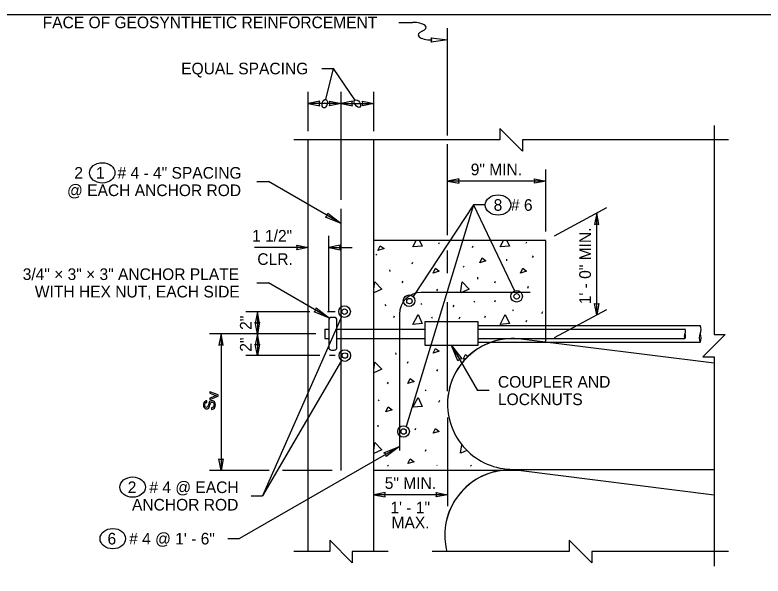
# Model space of a CAD drawing. Extents: x 99862 to 104211, y 98939 to 105076.
# Drawn here: x 100393 to 101422, y 104304 to 105076 of the extents above; entities that cross this region are included whole.
import ezdxf

# ---------------------------------------------------------------- set-up
doc = ezdxf.new("R2010")
doc.units = 0
for name, color, linetype in [('Level 1', 7, 'Continuous'), ('Level 10', 7, 'Continuous'), ('Level 15', 7, 'Continuous'), ('Level 16', 7, 'Continuous'), ('Level 19', 7, 'Continuous'), ('Level 20', 7, 'Continuous'), ('Level 24', 7, 'Continuous'), ('Level 3', 7, 'Continuous'), ('Level 6', 7, 'Continuous'), ('Level 8', 7, 'Continuous')]:
    doc.layers.add(name, color=color, linetype=linetype)

msp = doc.modelspace()

# ---------------------------------------------------------------- linework, layer by layer
at = {"layer": 'Level 1'}
msp.add_lwpolyline([(99862, 102999.5), (103151, 102999.5), (103151, 105075.5), (99862, 105075.5)], close=True, dxfattribs=at)
at = {"layer": 'Level 10'}
msp.add_line((100841.7, 104449), (100841.7, 104809), dxfattribs=at)
for points in [[(101101.9, 104693.9), (100951.9, 104693.9)], [(100921.9, 104663.9), (100921.9, 104476.4)]]:
    msp.add_lwpolyline(points, dxfattribs=at)
for centre in [(101083.1, 104688.5), (100935.7, 104681.9), (100846.5, 104667.4), (100846.9, 104607), (100927.6, 104502.5)]:
    msp.add_circle(centre, 3.75, dxfattribs=at)
msp.add_arc((100951.9, 104663.9), 30, 90, 180, dxfattribs=at)
at = {"layer": 'Level 15'}
for p, q in [((100921.2, 105065.2), (100939.8, 105065.2)), ((100988.2, 104909.6), (100988.2, 105057.2)), ((100815.1, 105001.8), (100831.1, 105001.8)), ((100820.6, 104959.4), (100831.1, 105001.8)), ((100860.8, 104958.6), (100831.1, 105001.8)), ((100796.7, 104915.6), (100796.7, 104969.6)), ((100841.7, 104821), (100841.7, 104969.6)), ((100886.7, 104915.6), (100886.7, 104969.6)), ((100841.7, 104953.6), (100886.7, 104953.6)), ((100988.2, 104772.6), (100988.2, 104897.6)), ((101123.2, 104777.4), (101123.2, 104863)), ((100725.9, 104846.3), (100741.9, 104846.3)), ((100841.7, 104788.7), (100741.9, 104846.3)), ((101123.2, 104847), (100988.2, 104847)), ((101024, 104814.1), (100931, 104509.6)), ((101024, 104814.1), (100940.9, 104688.1)), ((101040, 104814.1), (101024, 104814.1)), ((101024, 104814.1), (101080.3, 104696)), ((101135.2, 104771.8), (101207.3, 104810.5)), ((101193.2, 104663), (101193.2, 104802.9)), ((100824.8, 104667.7), (100824.8, 104771.7)), ((100796.7, 104755.7), (100722.8, 104755.7)), ((100824.8, 104755.7), (100856.8, 104755.7)), ((100988.2, 104720.5), (100988.2, 104751.5)), ((100725.9, 104706.9), (100741.9, 104706.9)), ((100825.9, 104658.4), (100741.9, 104706.9)), ((100988.2, 104557.8), (100988.2, 104680.6)), ((101135.2, 104631.9), (101207.3, 104670.5)), ((100799, 104667), (100710.7, 104667)), ((100726.7, 104667), (100726.7, 104637)), ((100842.5, 104660.3), (100733.9, 104413.8)), ((100833.4, 104667), (100823, 104667)), ((100807.2, 104637), (100660.7, 104637)), ((100676.7, 104637), (100676.7, 104449)), ((100726.7, 104637), (100726.7, 104607)), ((100993.6, 104620.7), (101029.4, 104558.8)), ((100812.4, 104607), (100710.7, 104607)), ((100833.4, 104607), (100825.6, 104607)), ((100842.5, 104600.2), (100733.9, 104413.8)), ((101045.4, 104558.8), (101029.4, 104558.8)), ((100988.2, 104521.8), (100988.2, 104399.6)), ((100921.9, 104482.1), (100702, 104355.1)), ((100742.9, 104449), (100660.7, 104449)), ((100829.7, 104449), (100761.2, 104449)), ((100717.9, 104413.8), (100733.9, 104413.8)), ((100988.2, 104415.6), (100886.7, 104415.6)), ((100686, 104355.1), (100702, 104355.1))]:
    msp.add_line(p, q, dxfattribs=at)
for points in [[(100988.2, 105041.2), (100965.4, 105038.2), (100966.4, 105041.2), (100965.4, 105044.2)], [(100796.7, 104953.6), (100812.4, 104950.5), (100811.7, 104953.6), (100812.4, 104956.7)], [(100841.7, 104953.6), (100826, 104950.5), (100826.7, 104953.6), (100826, 104956.7)], [(100841.7, 104953.6), (100857.4, 104950.5), (100856.7, 104953.6), (100857.4, 104956.7)], [(100886.7, 104953.6), (100871, 104950.5), (100871.7, 104953.6), (100871, 104956.7)], [(100988.2, 104847), (101003.9, 104843.9), (101003.2, 104847), (101003.9, 104850.1)], [(101123.2, 104847), (101107.5, 104843.9), (101108.2, 104847), (101107.5, 104850.1)], [(100841.7, 104788.7), (100820.4, 104797.5), (100822.8, 104799.6), (100823.4, 104802.7)], [(101193.2, 104802.9), (101190.1, 104787.2), (101193.2, 104788), (101196.3, 104787.2)], [(100796.7, 104755.7), (100781, 104752.6), (100781.7, 104755.7), (100781, 104758.8)], [(100824.8, 104755.7), (100840.5, 104752.6), (100839.8, 104755.7), (100840.5, 104758.8)], [(101193.2, 104663), (101190.1, 104678.7), (101193.2, 104678), (101196.3, 104678.7)], [(100825.9, 104658.4), (100804.6, 104667.2), (100807, 104669.3), (100807.6, 104672.4)], [(100726.7, 104667), (100723.6, 104651.2), (100726.7, 104652), (100729.8, 104651.2)], [(100726.7, 104637), (100723.6, 104652.7), (100726.7, 104652), (100729.8, 104652.7)], [(100676.7, 104637), (100673.6, 104621.2), (100676.7, 104622), (100679.8, 104621.2)], [(100726.7, 104637), (100723.6, 104621.2), (100726.7, 104622), (100729.8, 104621.2)], [(100726.7, 104607), (100723.6, 104622.7), (100726.7, 104622), (100729.8, 104622.7)], [(100993.6, 104620.7), (101007.6, 104602.5), (101004.5, 104601.9), (101002.4, 104599.5)], [(100921.9, 104482.1), (100903.6, 104468.1), (100903.1, 104471.2), (100900.7, 104473.3)], [(100676.7, 104449), (100673.6, 104464.7), (100676.7, 104464), (100679.8, 104464.7)], [(100886.7, 104415.6), (100902.4, 104412.5), (100901.7, 104415.6), (100902.4, 104418.6)], [(100988.2, 104415.6), (100972.5, 104412.5), (100973.2, 104415.6), (100972.5, 104418.6)]]:
    msp.add_lwpolyline(points, close=True, dxfattribs=at)
for points in [[(100841.7, 104953.6), (100796.7, 104953.6)], [(101374.5, 104903.6), (101091.1, 104903.6), (101091.1, 104888.1), (101060.1, 104919.1), (101060.1, 104903.6), (100776.7, 104903.6)], [(101354.5, 104923.6), (101354.5, 104636), (101370, 104636), (101339.1, 104605.1), (101354.5, 104605.1), (101354.5, 104317.5)], [(100906.7, 104337.5), (100857.2, 104337.5), (100857.2, 104322), (100826.2, 104353), (100826.2, 104337.5), (100776.7, 104337.5)], [(101374.5, 104337.5), (101186.3, 104337.5), (101186.3, 104322), (101155.3, 104353), (101155.3, 104337.5), (100967.1, 104337.5)]]:
    msp.add_lwpolyline(points, dxfattribs=at)
for centre in [(100935.3, 104682.4), (101083.1, 104688.5), (100846.5, 104667.4), (100846.9, 104607), (100927.6, 104502.5)]:
    msp.add_circle(centre, 8, dxfattribs=at)
for centre, start_param, end_param in [((100939.9, 105058.2), 5.497747, 7.861127), ((100966.4, 105048.2), 2.356226, 4.712389)]:
    msp.add_ellipse(centre, major_axis=(18.7, 0), ratio=0.375, start_param=start_param, end_param=end_param, dxfattribs=at)
for centre, major_axis in [((100819.2, 104953.6), (1.44, 5.82)), ((100864.2, 104953.6), (-3.4, 4.95))]:
    msp.add_ellipse(centre, major_axis=major_axis, ratio=0.57735, dxfattribs=at)
at = {"layer": 'Level 16'}
for p, q in [((100976.3, 104760.7), (100977.1, 104762.6)), ((101096.3, 104761.5), (101097.1, 104763.4)), ((101022.2, 104755.4), (101023.2, 104757.8)), ((100889.6, 104746.5), (100890.6, 104744.9)), ((101105.1, 104741.9), (101106.2, 104744.3)), ((100939.5, 104733.2), (100940.6, 104735.6)), ((101069, 104739.5), (101069.3, 104737.1)), ((100908.5, 104725.1), (100908.8, 104722.7)), ((101009.6, 104730), (101010.6, 104728.4)), ((101029.1, 104714.6), (101029.4, 104712.2)), ((100925.9, 104706.8), (100927, 104709.2)), ((101053.1, 104706.8), (101054.2, 104709.2)), ((101098.5, 104699.8), (101099.5, 104702.2)), ((100973.6, 104695.9), (100974.7, 104698.3)), ((100951.4, 104678.8), (100952.5, 104677.2)), ((101024.1, 104682.2), (101025.2, 104680.6)), ((101053.1, 104680.7), (101054.2, 104683.1)), ((100902.1, 104677), (100903.1, 104675.4)), ((100996, 104673.9), (100997, 104676.3)), ((101077.3, 104670.2), (101078.4, 104668.6)), ((100914.3, 104659.4), (100915.4, 104661.8)), ((100966, 104660.1), (100967.1, 104658.5)), ((101004.3, 104657.7), (101005.4, 104660.1)), ((101039.4, 104659.4), (101040.5, 104661.8)), ((101117.8, 104665), (101118.9, 104667.4)), ((101096.3, 104653.3), (101097.3, 104655.7)), ((100916.5, 104610.7), (100916.8, 104608.3)), ((100933.1, 104596.5), (100934.2, 104598.9)), ((100973.6, 104585.6), (100974.7, 104588)), ((100905.7, 104568.1), (100906.8, 104570.5)), ((100957.3, 104559.9), (100958.4, 104558.3)), ((100892.8, 104546.3), (100893.9, 104544.7)), ((100976.3, 104543), (100977.3, 104545.4)), ((100892.1, 104511.4), (100892.4, 104509)), ((100943.4, 104504.9), (100944.4, 104507.3)), ((100957.6, 104475.4), (100958.7, 104477.8)), ((100905.4, 104456.4), (100906.5, 104454.9)), ((100973.3, 104456.4), (100973.7, 104455.8)), ((101019.5, 104456.4), (101020.6, 104454.9))]:
    msp.add_line(p, q, dxfattribs=at)
for points in [[(100940.3, 104756.4), (100945.1, 104765.4)], [(100949.5, 104765.4), (100953.1, 104757.4), (100940.6, 104756.4)], [(101060.3, 104756.4), (101065.1, 104765.4)], [(101069.5, 104765.4), (101073.1, 104757.4), (101060.6, 104756.4)], [(100892.5, 104751.4), (100895.7, 104758.1), (100901.1, 104754.1), (100892.5, 104751.4)], [(101032.4, 104734.6), (101035.6, 104741.3), (101040.9, 104737.3), (101032.4, 104734.6)], [(100968.3, 104720.5), (100971.5, 104727.2), (100976.8, 104723.2), (100968.3, 104720.5)], [(101088.3, 104720.5), (101091.5, 104727.2), (101096.8, 104723.2), (101088.3, 104720.5)], [(100886.7, 104698.1), (100888.1, 104708.3), (100897.7, 104698.5), (100886.7, 104693.4)], [(101006, 104693.1), (101008.1, 104708.3), (101017.7, 104698.5), (101006.2, 104693.2)], [(100940.3, 104649.8), (100947.5, 104663.4), (100953.1, 104650.9), (100940.6, 104649.8)], [(101060.3, 104649.8), (101067.5, 104663.4), (101073.1, 104650.9), (101060.6, 104649.8)], [(100968.3, 104610.3), (100971.5, 104616.9), (100976.8, 104612.9), (100968.3, 104610.3)], [(101009.6, 104601.9), (101012.8, 104608.5), (101016.3, 104605.9)], [(100886.7, 104587.8), (100888.1, 104598.1), (100897.7, 104588.2), (100886.7, 104583.2)], [(101013.5, 104603.1), (101009.6, 104601.9)], [(100933.6, 104568.6), (100936.8, 104575.2), (100942.2, 104571.2), (100933.6, 104568.6)], [(100940.3, 104535.8), (100947.5, 104549.4), (100953.1, 104536.9), (100940.6, 104535.8)], [(100903.3, 104529.7), (100906.5, 104536.4), (100911.8, 104532.4), (100903.3, 104529.7)], [(100968.3, 104500), (100971.5, 104506.7), (100976.8, 104502.7), (100968.3, 104500)], [(100886.7, 104477), (100888.1, 104487.2), (100897.7, 104477.4), (100886.7, 104472.3)], [(101006, 104472.6), (101007.6, 104484.3)], [(101014.6, 104476.6), (101006.2, 104472.7)], [(100933.6, 104458.3), (100936.8, 104465), (100942.2, 104461), (100933.6, 104458.3)]]:
    msp.add_lwpolyline(points, dxfattribs=at)
at = {"layer": 'Level 19'}
msp.add_lwpolyline([(101078.4, 104449.6), (101078.4, 104450.4)], dxfattribs=at)
for centre, start, end in [((101078.1, 104540.4), 90.0973, 176.5425), ((101078.1, 104540.4), 176.5425, 270.21), ((101074.3, 104359.7), 87.4147, 176.5425), ((101074.3, 104359.7), 176.5425, 194.2759)]:
    msp.add_arc(centre, 90, start, end, dxfattribs=at)
at = {"layer": 'Level 20'}
for centre in [(100513.4, 104858.3), (101057.5, 104814.1), (100555.2, 104426), (100527.9, 104355.1)]:
    msp.add_ellipse(centre, major_axis=(-17.5, 0), ratio=0.8, dxfattribs=at)
at = {"layer": 'Level 24'}
msp.add_line((101078.4, 104450.4), (101354.5, 104450.4), dxfattribs=at)
for points in [[(101354.5, 104596.3), (101089.2, 104629.7)], [(101354.5, 104415.1), (101085.5, 104449)]]:
    msp.add_lwpolyline(points, dxfattribs=at)
for centre, start, end in [((101078.1, 104540.4), 82.875, 176.5425), ((101078.1, 104540.4), 176.5425, 270.21), ((101074.3, 104359.7), 82.875, 176.5425), ((101074.3, 104359.7), 176.5425, 194.276)]:
    msp.add_arc(centre, 90, start, end, dxfattribs=at)
at = {"layer": 'Level 3'}
for p, q in [((100796.7, 104337.5), (100796.7, 104903.6)), ((100886.7, 104337.5), (100886.7, 104903.6))]:
    msp.add_line(p, q, dxfattribs=at)
for points in [[(100672.6, 104550.9), (100672.6, 104552.8), (100661.1, 104557.1), (100661.1, 104555.2), (100668.1, 104552.5), (100670.3, 104551.8), (100668, 104551.1), (100661.1, 104548.4), (100661.1, 104546.5)], [(100663.5, 104532.9), (100665, 104533.2), (100666.3, 104533.8), (100667.5, 104534.7), (100668.3, 104535.9), (100668.7, 104537.5), (100668.9, 104539.4), (100668.7, 104540.9), (100668.3, 104542.3), (100667.5, 104543.5), (100666.5, 104544.3), (100665.4, 104544.8), (100664.2, 104545), (100663, 104544.8), (100661.9, 104544.4), (100661, 104543.6), (100660.3, 104542.4), (100659.3, 104539.1), (100658.7, 104537.2), (100658.2, 104536.2), (100657.6, 104535.8), (100656.8, 104535.6), (100655.9, 104535.8), (100655.1, 104536.5), (100654.6, 104537.5), (100654.4, 104539), (100654.6, 104540.5), (100655.1, 104541.6), (100655.9, 104542.3), (100657.1, 104542.6), (100657.1, 104544.7), (100655.9, 104544.5), (100654.7, 104544), (100653.8, 104543.1), (100653.1, 104541.9), (100652.7, 104540.5), (100652.6, 104538.9), (100652.7, 104537.5), (100653.1, 104536.1), (100653.8, 104535), (100654.7, 104534.2), (100655.8, 104533.7), (100656.9, 104533.5), (100658, 104533.7), (100658.9, 104534.1), (100659.7, 104534.8), (100660.4, 104535.8), (100660.9, 104537), (100661.4, 104538.7), (100662.1, 104541.3), (100662.6, 104542.1), (100663.1, 104542.6), (100663.7, 104542.8), (100664.4, 104542.9), (100665.1, 104542.8), (100665.8, 104542.5), (100666.3, 104542), (100666.7, 104541.2), (100667, 104540.3), (100667.1, 104539.3), (100667, 104538.1), (100666.6, 104537.1), (100666.1, 104536.2), (100665.4, 104535.6), (100664.5, 104535.3), (100663.5, 104535)]]:
    msp.add_lwpolyline(points, close=True, dxfattribs=at)
at = {"layer": 'Level 6'}
for p, q in [((101123.2, 104765.4), (100886.7, 104765.4)), ((101123.2, 104625.4), (101123.2, 104765.4)), ((101085.5, 104449), (100886.7, 104449))]:
    msp.add_line(p, q, dxfattribs=at)
at = {"layer": 'Level 8'}
for p, q in [((100832.3, 104659.5), (100828.5, 104659.5)), ((100824.8, 104655.7), (100824.8, 104618.2)), ((100836, 104618.2), (100836, 104655.7)), ((101029.9, 104648.5), (101335.4, 104648.5)), ((100819.2, 104643.5), (100819.2, 104630.4)), ((100819.2, 104643.5), (100824.8, 104643.5)), ((100836, 104643.5), (100957.3, 104643.5)), ((101029.9, 104643.5), (101314.4, 104643.5)), ((100819.2, 104630.4), (100824.8, 104630.4)), ((100836, 104630.4), (100957.3, 104630.4)), ((101029.9, 104630.4), (101314.4, 104630.4)), ((101029.9, 104625.4), (101335.4, 104625.4)), ((100828.5, 104614.5), (100832.3, 104614.5))]:
    msp.add_line(p, q, dxfattribs=at)
msp.add_lwpolyline([(100957.3, 104653.7), (101029.9, 104653.7), (101029.9, 104620.7), (100957.3, 104620.7)], close=True, dxfattribs=at)
for centre, radius, start, end in [((100828.5, 104655.7), 3.75, 90, 180), ((100832.3, 104655.7), 3.75, 0, 90), ((101325.4, 104642.7), 11.5, 330, 30), ((101308.7, 104640.3), 6.56, 330, 30), ((101320.1, 104633.7), 6.56, 150, 210), ((101308.7, 104633.7), 6.56, 330, 30), ((101345.4, 104631.2), 11.5, 150, 210), ((101325.4, 104631.2), 11.5, 330, 30), ((100828.5, 104618.2), 3.75, 180, 270), ((100832.3, 104618.2), 3.75, 270, 0)]:
    msp.add_arc(centre, radius, start, end, dxfattribs=at)

# ---------------------------------------------------------------- texts
at = {"layer": 'Level 20'}
for s, p in [('FACE OF GEOSYNTHETIC REINFORCEMENT', (100431.5, 105057.2)), ('EQUAL SPACING', (100621.9, 104993.8)), ('2   1   # 4 - 4" SPACING', (100475, 104850.3)), ('9" MIN.', (101020, 104855)), ('@ EACH ANCHOR ROD', (100465, 104826.3)), ('1 1/2"', (100719.3, 104763.7)), ('CLR.', (100726.6, 104731.7)), (' 3/4" × 3" × 3" ANCHOR PLATE ', (100398.1, 104710.9)), ('WITH HEX NUT, EACH SIDE', (100420.7, 104686.9)), ('2   # 4 @ EACH', (100548.4, 104417.8)), ('5" MIN.', (100901.8, 104423.6)), ('ANCHOR ROD', (100554.3, 104393.8)), ('1\' - 1"', (100909.5, 104389.9)), ('MAX.', (100911.1, 104369.2)), (' 6   # 4 @ 1\' - 6"', (100514.7, 104347.1))]:
    msp.add_text(s, height=16, dxfattribs=at).set_placement(p)
for s, rotation, p in [('8  # 6', 360, (101051.5, 104806.1)), ('1\' - 0" MIN.', 90, (101185.2, 104677.5)), ('2"', 90, (100718.7, 104642.3)), ('2"', 90, (100718.7, 104612.3)), ('COUPLER AND', 360, (101057.4, 104562.8)), ('LOCKNUTS', 360, (101057.4, 104538.8))]:
    msp.add_text(s, height=16, rotation=rotation, dxfattribs=at).set_placement(p)

doc.saveas('drawing.dxf')
